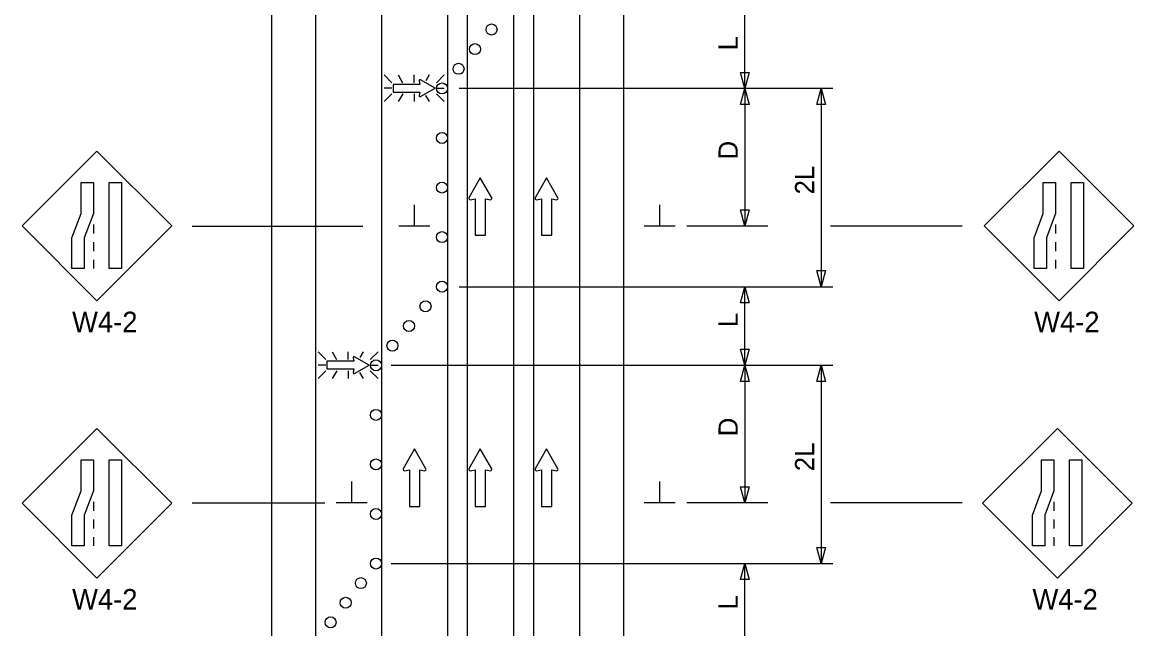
# Model space of a CAD drawing. Extents: x 16726 to 18479, y 5932 to 7023.
# Drawn here: x 16768.2 to 17172, y 6511.8 to 6732.2 of the extents above; entities that cross this region are included whole.
import ezdxf

# ---------------------------------------------------------------- set-up
doc = ezdxf.new("R2010")
doc.units = 0
for name, color, linetype in [('ALI_LEGAL_EX', 7, 'Continuous'), ('MT_SCRATCH_LEVEL_E', 7, 'Continuous'), ('PAVT_EDGE_EX', 7, 'Continuous'), ('TRAFFIC_SIGNS_PR', 7, 'Continuous'), ('TYPICAL_TEXT_DIMEN_PR', 7, 'Continuous')]:
    doc.layers.add(name, color=color, linetype=linetype)

msp = doc.modelspace()

# ---------------------------------------------------------------- linework, layer by layer
at = {"layer": 'ALI_LEGAL_EX'}
for p, q in [((16898.69, 7022.86), (16898.69, 6323.13)), ((16922.69, 7022.86), (16922.69, 6323.13)), ((16946.69, 7022.86), (16946.69, 6323.13)), ((16929.88, 7005.57), (16929.88, 6176.39)), ((16953.88, 7005.57), (16953.88, 6176.39)), ((16953.88, 7005.57), (16953.88, 6176.39))]:
    msp.add_line(p, q, dxfattribs=at)
for points in [[(16898.69, 6682.86), (16898.69, 6657.86)], [(16922.69, 6682.86), (16922.69, 6657.86)], [(16946.69, 6682.86), (16946.69, 6657.86)], [(16898.69, 6582.86), (16898.69, 6557.86)], [(16922.69, 6582.86), (16922.69, 6557.86)], [(16946.69, 6582.86), (16946.69, 6557.86)]]:
    msp.add_lwpolyline(points, dxfattribs=at)
at = {"layer": 'MT_SCRATCH_LEVEL_E'}
for p, q in [((16934.6, 6675.63), (16930.49, 6668.39)), ((16938.74, 6668.39), (16934.6, 6675.63)), ((16958.65, 6675.63), (16954.54, 6668.39)), ((16962.8, 6668.39), (16958.65, 6675.63)), ((16930.97, 6667.71), (16932.74, 6668.02)), ((16932.74, 6668.02), (16932.74, 6654.77)), ((16936.49, 6654.77), (16936.49, 6668.02)), ((16936.49, 6668.02), (16938.26, 6667.71)), ((16955.02, 6667.71), (16956.8, 6668.02)), ((16956.8, 6668.02), (16956.8, 6654.77)), ((16960.54, 6654.77), (16960.54, 6668.02)), ((16960.54, 6668.02), (16962.32, 6667.71)), ((16932.74, 6654.77), (16936.49, 6654.77)), ((16956.8, 6654.77), (16960.54, 6654.77)), ((16910.69, 6577.17), (16906.58, 6569.93)), ((16914.84, 6569.93), (16910.69, 6577.17)), ((16934.6, 6577.17), (16930.49, 6569.93)), ((16938.74, 6569.93), (16934.6, 6577.17)), ((16958.65, 6577.17), (16954.54, 6569.93)), ((16962.8, 6569.93), (16958.65, 6577.17)), ((16907.06, 6569.24), (16908.84, 6569.56)), ((16908.84, 6569.56), (16908.84, 6556.3)), ((16912.58, 6556.3), (16912.58, 6569.56)), ((16912.58, 6569.56), (16914.36, 6569.24)), ((16930.97, 6569.24), (16932.74, 6569.56)), ((16932.74, 6569.56), (16932.74, 6556.3)), ((16936.49, 6556.3), (16936.49, 6569.56)), ((16936.49, 6569.56), (16938.26, 6569.24)), ((16955.02, 6569.24), (16956.8, 6569.56)), ((16956.8, 6569.56), (16956.8, 6556.3)), ((16960.54, 6556.3), (16960.54, 6569.56)), ((16960.54, 6569.56), (16962.32, 6569.24)), ((16908.84, 6556.3), (16912.58, 6556.3)), ((16932.74, 6556.3), (16936.49, 6556.3)), ((16956.8, 6556.3), (16960.54, 6556.3))]:
    msp.add_line(p, q, dxfattribs=at)
for centre, start, end in [((16930.89, 6668.17), 150.4248, 279.9638), ((16938.33, 6668.17), 260.0362, 29.7731), ((16954.95, 6668.17), 150.4248, 279.9638), ((16962.39, 6668.17), 260.0362, 29.7731), ((16906.99, 6569.7), 150.4248, 279.9638), ((16914.43, 6569.7), 260.0362, 29.7731), ((16930.89, 6569.7), 150.4248, 279.9638), ((16938.33, 6569.7), 260.0362, 29.7731), ((16954.95, 6569.7), 150.4248, 279.9638), ((16962.39, 6569.7), 260.0362, 29.7731)]:
    msp.add_arc(centre, 0.463, start, end, dxfattribs=at)
at = {"layer": 'PAVT_EDGE_EX'}
for p, q in [((16858.69, 6927.61), (16858.69, 6215.05)), ((16874.69, 6927.61), (16874.69, 6215.05)), ((16970.69, 6927.61), (16970.69, 6215.05)), ((16986.69, 6927.61), (16986.69, 6215.05))]:
    msp.add_line(p, q, dxfattribs=at)
at = {"layer": 'TRAFFIC_SIGNS_PR'}
for p, q in [((16902.47, 6710.21), (16899.65, 6713.03)), ((16904.77, 6713.03), (16906.39, 6710.21)), ((16910.55, 6710.21), (16910.55, 6713.03)), ((16916.02, 6713.03), (16914.82, 6710.94)), ((16921.46, 6713.03), (16918.64, 6710.21)), ((16902.47, 6708.18), (16899.65, 6708.18)), ((16902.47, 6706.15), (16899.65, 6703.32)), ((16906.42, 6706.15), (16904.79, 6703.33)), ((16910.55, 6706.15), (16910.55, 6703.33)), ((16914.74, 6705.51), (16916, 6703.33)), ((16918.64, 6708.18), (16921.46, 6708.18)), ((16921.46, 6703.33), (16918.64, 6706.15)), ((16795.32, 6685.32), (16768.17, 6658.17)), ((16822.47, 6658.17), (16795.32, 6685.32)), ((17144.88, 6685.32), (17117.73, 6658.17)), ((17172.03, 6658.17), (17144.88, 6685.32)), ((16768.17, 6658.17), (16795.32, 6631.02)), ((16794.07, 6658.66), (16794.07, 6655.46)), ((16795.32, 6631.02), (16822.47, 6658.17)), ((17117.73, 6658.17), (17144.88, 6631.02)), ((17143.63, 6658.66), (17143.63, 6655.46)), ((17144.88, 6631.02), (17172.03, 6658.17)), ((16794.07, 6652.26), (16794.07, 6649.06)), ((17143.63, 6652.26), (17143.63, 6649.06)), ((16794.07, 6645.86), (16794.07, 6642.66)), ((17143.63, 6645.86), (17143.63, 6642.66)), ((16878.47, 6609.65), (16875.65, 6612.47)), ((16880.77, 6612.47), (16882.39, 6609.65)), ((16886.55, 6609.65), (16886.55, 6612.47)), ((16892.02, 6612.47), (16890.82, 6610.37)), ((16897.46, 6612.47), (16894.64, 6609.65)), ((16878.47, 6607.61), (16875.65, 6607.61)), ((16894.64, 6607.61), (16897.46, 6607.61)), ((16878.47, 6605.58), (16875.65, 6602.76)), ((16882.42, 6605.58), (16880.79, 6602.76)), ((16886.55, 6605.58), (16886.55, 6602.76)), ((16890.74, 6604.95), (16892, 6602.76)), ((16897.46, 6602.77), (16894.64, 6605.58)), ((16795.32, 6584.57), (16768.17, 6557.42)), ((16822.47, 6557.42), (16795.32, 6584.57)), ((17144.26, 6584.57), (17117.11, 6557.42)), ((17171.42, 6557.42), (17144.26, 6584.57)), ((16768.17, 6557.42), (16795.32, 6530.27)), ((16794.07, 6557.91), (16794.07, 6554.71)), ((16795.32, 6530.27), (16822.47, 6557.42)), ((17117.11, 6557.42), (17144.26, 6530.27)), ((17143.02, 6557.91), (17143.02, 6554.71)), ((17144.26, 6530.27), (17171.42, 6557.42)), ((16794.07, 6551.51), (16794.07, 6548.31)), ((17143.02, 6551.51), (17143.02, 6548.31)), ((16794.07, 6545.11), (16794.07, 6541.91)), ((17143.02, 6545.11), (17143.02, 6541.91))]:
    msp.add_line(p, q, dxfattribs=at)
for points in [[(16912.38, 6710.86), (16912.61, 6709.56), (16902.89, 6709.56), (16902.89, 6706.82), (16912.61, 6706.82), (16912.38, 6705.52)], [(16912.88, 6705.16), (16918.19, 6708.18), (16912.88, 6711.22)], [(16888.38, 6610.3), (16888.61, 6609), (16878.89, 6609), (16878.89, 6606.26), (16888.61, 6606.26), (16888.38, 6604.95)], [(16888.88, 6604.6), (16894.19, 6607.61), (16888.88, 6610.66)]]:
    msp.add_lwpolyline(points, dxfattribs=at)
for points in [[(16794.07, 6673.91), (16794.07, 6662.73), (16790.73, 6653.84), (16790.73, 6642.66), (16786.24, 6642.66), (16786.24, 6653.84), (16789.58, 6662.73), (16789.58, 6673.91)], [(16804.21, 6673.91), (16804.21, 6642.66), (16799.72, 6642.66), (16799.72, 6673.91)], [(17143.63, 6673.91), (17143.63, 6662.73), (17140.29, 6653.84), (17140.29, 6642.66), (17135.79, 6642.66), (17135.79, 6653.84), (17139.14, 6662.73), (17139.14, 6673.91)], [(17153.77, 6673.91), (17153.77, 6642.66), (17149.27, 6642.66), (17149.27, 6673.91)], [(16794.07, 6573.16), (16794.07, 6561.98), (16790.73, 6553.09), (16790.73, 6541.91), (16786.24, 6541.91), (16786.24, 6553.09), (16789.58, 6561.98), (16789.58, 6573.16)], [(16804.21, 6573.16), (16804.21, 6541.91), (16799.72, 6541.91), (16799.72, 6573.16)], [(17143.02, 6573.16), (17143.02, 6561.98), (17139.67, 6553.09), (17139.67, 6541.91), (17135.18, 6541.91), (17135.18, 6553.09), (17138.52, 6561.98), (17138.52, 6573.16)], [(17153.15, 6573.16), (17153.15, 6541.91), (17148.66, 6541.91), (17148.66, 6573.16)]]:
    msp.add_lwpolyline(points, close=True, dxfattribs=at)
for centre in [(16938.69, 6729.53), (16932.69, 6722.39), (16926.69, 6715.25), (16920.69, 6708.11), (16920.69, 6690.11), (16920.69, 6672.11), (16920.69, 6654.11), (16920.69, 6636.11), (16914.69, 6628.97), (16908.69, 6621.83), (16902.69, 6614.69), (16896.69, 6607.55), (16896.69, 6589.54), (16896.69, 6571.54), (16896.69, 6553.54), (16896.69, 6535.54), (16891.2, 6528.41), (16885.7, 6521.29), (16880.2, 6514.16)]:
    msp.add_circle(centre, 2, dxfattribs=at)
for centre, start, end in [((16912.72, 6710.92), 61.4833, 189.9593), ((16912.72, 6705.46), 170.7308, 298.8916), ((16888.72, 6610.36), 61.4833, 189.9593), ((16888.72, 6604.9), 170.7308, 298.8916)]:
    msp.add_arc(centre, 0.341, start, end, dxfattribs=at)
at = {"layer": 'TYPICAL_TEXT_DIMEN_PR'}
for p, q in [((17030.69, 6708.11), (17030.69, 6738.67)), ((17030.69, 6708.11), (17029.12, 6713.97)), ((17029.12, 6713.97), (17030.69, 6713.97)), ((17030.69, 6713.97), (17032.26, 6713.97)), ((17032.26, 6713.97), (17030.69, 6708.11)), ((17062.74, 6708.11), (16926.92, 6708.11)), ((17029.12, 6702.24), (17030.69, 6708.11)), ((17030.69, 6708.11), (17030.69, 6658.11)), ((17030.69, 6708.11), (17032.26, 6702.24)), ((17056.93, 6702.24), (17058.5, 6708.11)), ((17058.5, 6708.11), (17060.07, 6702.24)), ((17058.5, 6708.11), (17058.5, 6636.11)), ((17030.69, 6702.24), (17029.12, 6702.24)), ((17032.26, 6702.24), (17030.69, 6702.24)), ((17058.5, 6702.24), (17056.93, 6702.24)), ((17060.07, 6702.24), (17058.5, 6702.24)), ((16910.64, 6658.11), (16910.64, 6665.89)), ((16999.82, 6658.11), (16999.82, 6665.89)), ((17030.69, 6658.11), (17029.12, 6663.97)), ((17029.12, 6663.97), (17030.69, 6663.97)), ((17030.69, 6663.97), (17032.26, 6663.97)), ((17032.26, 6663.97), (17030.69, 6658.11)), ((17058.5, 6662.98), (17058.5, 6659.21)), ((16829.94, 6658.11), (16891.95, 6658.11)), ((16916.26, 6658.11), (16905.01, 6658.11)), ((17005.44, 6658.11), (16994.19, 6658.11)), ((17039.11, 6658.11), (17009.69, 6658.11)), ((17109.74, 6658.11), (17061.87, 6658.11)), ((17058.5, 6636.11), (17056.93, 6641.97)), ((17056.93, 6641.97), (17058.5, 6641.97)), ((17058.5, 6641.97), (17060.07, 6641.97)), ((17060.07, 6641.97), (17058.5, 6636.11)), ((16926.92, 6636.11), (17062.74, 6636.11)), ((17029.12, 6630.24), (17030.69, 6636.11)), ((17030.69, 6607.55), (17030.69, 6636.11)), ((17030.69, 6636.11), (17032.26, 6630.24)), ((17030.69, 6630.24), (17029.12, 6630.24)), ((17032.26, 6630.24), (17030.69, 6630.24)), ((17030.69, 6607.55), (17029.12, 6613.41)), ((17029.12, 6613.41), (17030.69, 6613.41)), ((17030.69, 6613.41), (17032.26, 6613.41)), ((17032.26, 6613.41), (17030.69, 6607.55)), ((16902.24, 6607.55), (17062.74, 6607.55)), ((17029.12, 6601.68), (17030.69, 6607.55)), ((17030.69, 6607.55), (17030.69, 6557.55)), ((17030.69, 6607.55), (17032.26, 6601.68)), ((17056.93, 6601.68), (17058.5, 6607.55)), ((17058.5, 6607.55), (17060.07, 6601.68)), ((17058.5, 6607.55), (17058.5, 6535.55)), ((17030.69, 6601.68), (17029.12, 6601.68)), ((17032.26, 6601.68), (17030.69, 6601.68)), ((17058.5, 6601.68), (17056.93, 6601.68)), ((17060.07, 6601.68), (17058.5, 6601.68)), ((16887.91, 6557.55), (16887.91, 6565.33)), ((16999.82, 6557.55), (16999.82, 6565.33)), ((17030.69, 6557.55), (17029.12, 6563.41)), ((17029.12, 6563.41), (17030.69, 6563.41)), ((17030.69, 6563.41), (17032.26, 6563.41)), ((17032.26, 6563.41), (17030.69, 6557.55)), ((17058.5, 6562.41), (17058.5, 6558.65)), ((16829.94, 6557.55), (16878.12, 6557.55)), ((16893.53, 6557.55), (16882.28, 6557.55)), ((17005.44, 6557.55), (16994.19, 6557.55)), ((17039.11, 6557.55), (17009.69, 6557.55)), ((17109.74, 6557.55), (17061.87, 6557.55)), ((17058.5, 6535.55), (17056.93, 6541.41)), ((17056.93, 6541.41), (17058.5, 6541.41)), ((17058.5, 6541.41), (17060.07, 6541.41)), ((17060.07, 6541.41), (17058.5, 6535.55)), ((16902.24, 6535.54), (17062.74, 6535.54)), ((17029.12, 6529.68), (17030.69, 6535.54)), ((17030.69, 6504.98), (17030.69, 6535.54)), ((17030.69, 6535.54), (17032.26, 6529.68)), ((17030.69, 6529.68), (17029.12, 6529.68)), ((17032.26, 6529.68), (17030.69, 6529.68))]:
    msp.add_line(p, q, dxfattribs=at)

# ---------------------------------------------------------------- texts
at = {"layer": 'TRAFFIC_SIGNS_PR'}
for p in [(16786.28, 6619.58), (17135.84, 6619.58), (16786.28, 6518.83), (17135.22, 6518.83)]:
    msp.add_text('W4-2', height=7.44, dxfattribs=at).set_placement(p)
at = {"layer": 'TYPICAL_TEXT_DIMEN_PR'}
for s, p in [('L', (17028.14, 6721.96)), ('D', (17028.14, 6682.33)), ('2L', (17055.94, 6669.61)), ('L', (17028.14, 6621.4)), ('D', (17028.14, 6581.76)), ('2L', (17055.94, 6569.05)), ('L', (17028.14, 6518.84))]:
    msp.add_text(s, height=7, rotation=90, dxfattribs=at).set_placement(p)

doc.saveas('drawing.dxf')
